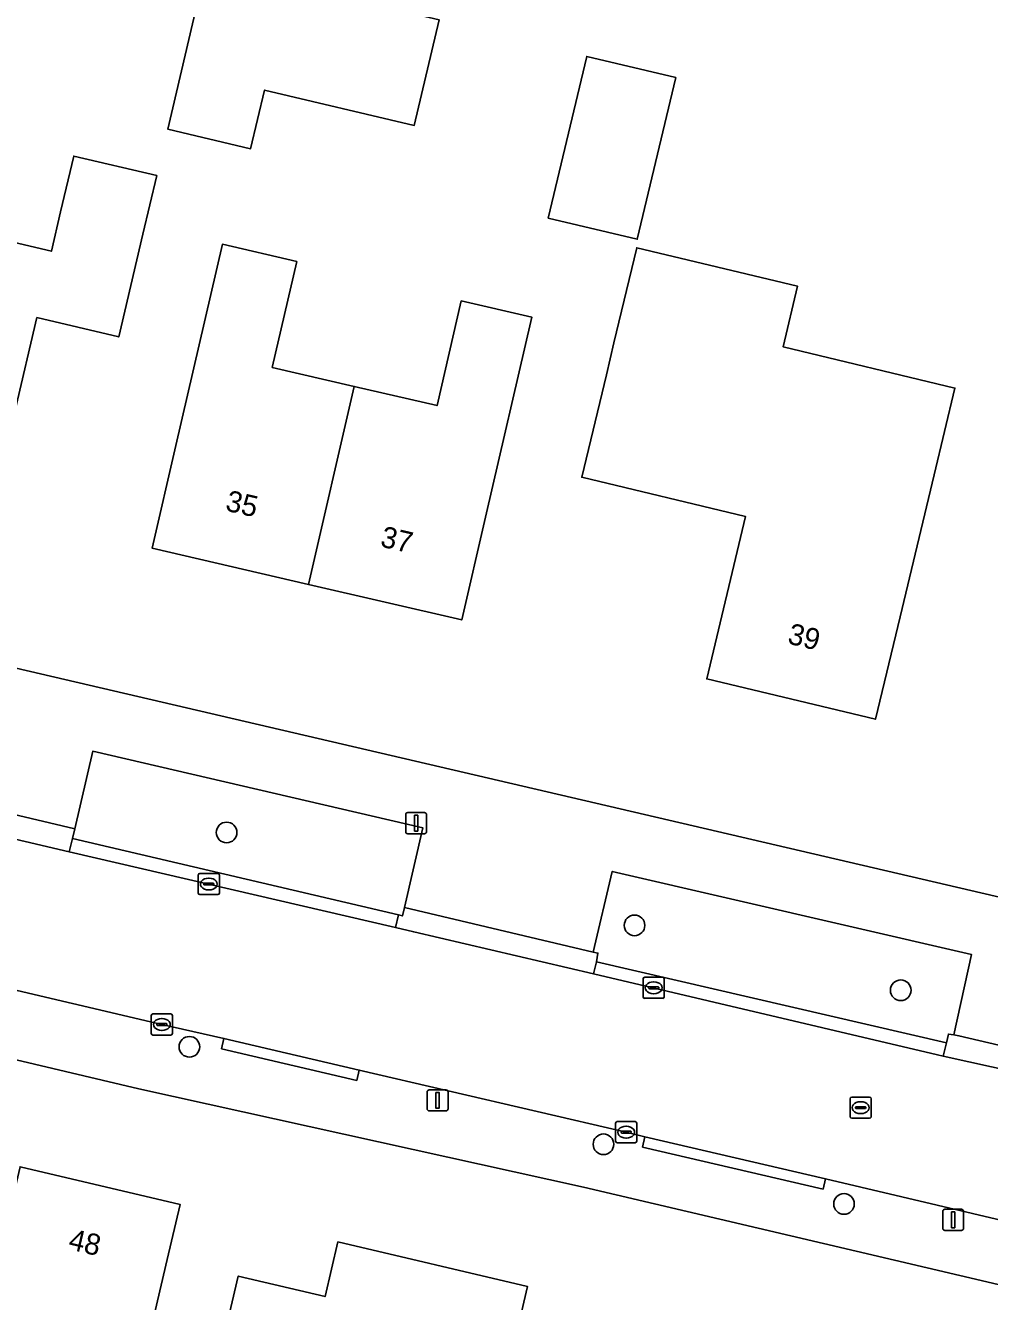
# Model space of a CAD drawing. Extents: x 162184 to 163154, y 385507 to 386516.
# Drawn here: x 162630.3 to 162676, y 385817.6 to 385878.1 of the extents above; entities that cross this region are included whole.
import ezdxf

# ---------------------------------------------------------------- set-up
doc = ezdxf.new("R2010")
doc.units = 0
for name, color, linetype in [('IMGEO_Boom', 7, 'Continuous'), ('IMGEO_Erf', 7, 'Continuous'), ('IMGEO_Groenvoorziening', 7, 'Continuous'), ('IMGEO_Kolk', 7, 'Continuous'), ('IMGEO_Lichtmast', 7, 'Continuous'), ('IMGEO_Pand', 7, 'Continuous'), ('IMGEO_Pand_nummerreeks', 7, 'Continuous'), ('IMGEO_Rijbaan_lokaal_open', 7, 'Continuous'), ('IMGEO_Rioolput', 7, 'Continuous'), ('IMGEO_Voetpad_open', 7, 'Continuous')]:
    doc.layers.add(name, color=color, linetype=linetype)

msp = doc.modelspace()

# ---------------------------------------------------------------- linework, layer by layer
at = {"layer": 'IMGEO_Boom'}
for centre in [(162639.821, 385839.799), (162659.165, 385835.397), (162671.791, 385832.319), (162638.057, 385829.641), (162657.693, 385825.018), (162669.1, 385822.191)]:
    msp.add_circle(centre, 0.489, dxfattribs=at)
at = {"layer": 'IMGEO_Erf'}
for points in [[(162649.904, 385878.319), (162648.723, 385873.317), (162641.619, 385874.994), (162640.961, 385872.21), (162637.027, 385873.14), (162638.858, 385880.909)], [(162519.391, 385873.302), (162708.853, 385829.198)], [(162699.173, 385813.033), (162656.753, 385822.985), (162635.665, 385827.646), (162589.44, 385838.573), (162506.371, 385857.936)], [(162630.025, 385823.952), (162637.617, 385822.17), (162637.005, 385819.56), (162636.146, 385815.902), (162639.516, 385815.111), (162640.375, 385818.769), (162644.49, 385817.803), (162645.097, 385820.389), (162654.087, 385818.279), (162652.945, 385813.412), (162651.884, 385808.893), (162645.19, 385810.464), (162644.958, 385809.475), (162643.186, 385809.891), (162642.433, 385806.685), (162638.063, 385807.711), (162638.332, 385808.855), (162638.219, 385808.881), (162638.703, 385810.943), (162638.545, 385810.98), (162638.06, 385808.918), (162632.544, 385810.213), (162633.135, 385812.73), (162627.689, 385814.008)]]:
    msp.add_lwpolyline(points, dxfattribs=at)
for points in [[(162656.896, 385876.589), (162661.118, 385875.584), (162659.295, 385867.92), (162655.073, 385868.925)], [(162636.506, 385870.937), (162635.85, 385868.163), (162634.707, 385863.295), (162630.822, 385864.207), (162629.793, 385859.826), (162628.67, 385855.046), (162625.13, 385855.878), (162625.383, 385856.954), (162621.583, 385857.847), (162617.805, 385858.735), (162617.558, 385857.684), (162613.986, 385858.523), (162615.13, 385863.391), (162616.916, 385870.993), (162620.447, 385870.164), (162619.874, 385867.725), (162623.666, 385866.834), (162627.538, 385865.924), (162628.065, 385868.165), (162631.511, 385867.355), (162631.948, 385869.215), (162632.571, 385871.867)], [(162650.951, 385864.998), (162654.298, 385864.223), (162652.101, 385854.745), (162650.972, 385849.874), (162643.7, 385851.559), (162636.284, 385853.278), (162637.413, 385858.149), (162639.622, 385867.681), (162643.148, 385866.864), (162641.984, 385861.844), (162645.875, 385860.943), (162649.801, 385860.033)], [(162659.273, 385867.519), (162666.898, 385865.69), (162666.21, 385862.822), (162674.357, 385860.869), (162673.37, 385856.753), (162671.758, 385850.028), (162670.593, 385845.165), (162662.591, 385847.083), (162664.435, 385854.773), (162656.664, 385856.636), (162657.829, 385861.499), (162658.191, 385863.008)]]:
    msp.add_lwpolyline(points, close=True, dxfattribs=at)
at = {"layer": 'IMGEO_Groenvoorziening'}
for points in [[(162649.129, 385840.013), (162633.475, 385843.651), (162632.616, 385839.977), (162632.507, 385839.511), (162647.978, 385835.893), (162648.161, 385835.843), (162648.254, 385836.243)], [(162675.153, 385834.012), (162658.107, 385837.957), (162657.207, 385834.121), (162657.428, 385834.085), (162657.358, 385833.668), (162673.955, 385829.832), (162674.055, 385830.239), (162674.313, 385830.2)]]:
    msp.add_lwpolyline(points, close=True, dxfattribs=at)
at = {"layer": 'IMGEO_Kolk'}
for p, q in [((162638.475, 385836.928), (162638.475, 385837.78)), ((162638.55, 385837.854), (162639.402, 385837.854)), ((162638.734, 385837.348), (162638.734, 385837.36)), ((162638.777, 385837.397), (162639.175, 385837.397)), ((162638.963, 385837.634), (162638.988, 385837.634)), ((162639.218, 385837.36), (162639.218, 385837.348)), ((162639.476, 385837.78), (162639.476, 385836.928)), ((162639.402, 385836.854), (162638.55, 385836.854)), ((162639.172, 385837.311), (162638.774, 385837.311)), ((162638.986, 385837.074), (162638.961, 385837.074)), ((162659.575, 385832.012), (162659.575, 385832.864)), ((162659.65, 385832.938), (162660.502, 385832.938)), ((162660.063, 385832.718), (162660.088, 385832.718)), ((162660.576, 385832.864), (162660.576, 385832.012)), ((162660.502, 385831.938), (162659.65, 385831.938)), ((162659.834, 385832.432), (162659.834, 385832.444)), ((162660.272, 385832.395), (162659.874, 385832.395)), ((162659.877, 385832.481), (162660.275, 385832.481)), ((162660.086, 385832.158), (162660.061, 385832.158)), ((162660.318, 385832.444), (162660.318, 385832.432)), ((162636.249, 385830.272), (162636.249, 385831.124)), ((162636.324, 385831.198), (162637.176, 385831.198)), ((162636.508, 385830.692), (162636.508, 385830.704)), ((162636.551, 385830.741), (162636.949, 385830.741)), ((162636.737, 385830.978), (162636.762, 385830.978)), ((162636.992, 385830.704), (162636.992, 385830.692)), ((162637.25, 385831.124), (162637.25, 385830.272)), ((162637.176, 385830.198), (162636.324, 385830.198)), ((162636.946, 385830.655), (162636.548, 385830.655)), ((162636.76, 385830.418), (162636.735, 385830.418)), ((162658.27, 385825.166), (162658.27, 385826.018)), ((162658.345, 385826.092), (162659.197, 385826.092)), ((162658.758, 385825.872), (162658.783, 385825.872)), ((162659.271, 385826.018), (162659.271, 385825.166)), ((162658.529, 385825.586), (162658.529, 385825.598)), ((162658.967, 385825.549), (162658.569, 385825.549)), ((162658.572, 385825.635), (162658.97, 385825.635)), ((162658.781, 385825.312), (162658.756, 385825.312)), ((162659.013, 385825.598), (162659.013, 385825.586)), ((162659.197, 385825.092), (162658.345, 385825.092))]:
    msp.add_line(p, q, dxfattribs=at)
for points in [[(162638.475, 385836.928), (162638.475, 385837.78)], [(162638.55, 385837.854), (162639.402, 385837.854)], [(162639.476, 385837.78), (162639.476, 385836.928)], [(162639.402, 385836.854), (162638.55, 385836.854)], [(162659.575, 385832.012), (162659.575, 385832.864)], [(162659.65, 385832.938), (162660.502, 385832.938)], [(162660.576, 385832.864), (162660.576, 385832.012)], [(162660.502, 385831.938), (162659.65, 385831.938)], [(162636.249, 385830.272), (162636.249, 385831.124)], [(162636.324, 385831.198), (162637.176, 385831.198)], [(162637.25, 385831.124), (162637.25, 385830.272)], [(162637.176, 385830.198), (162636.324, 385830.198)], [(162658.27, 385825.166), (162658.27, 385826.018)], [(162658.345, 385826.092), (162659.197, 385826.092)], [(162659.271, 385826.018), (162659.271, 385825.166)], [(162659.197, 385825.092), (162658.345, 385825.092)]]:
    msp.add_lwpolyline(points, dxfattribs=at)
for centre, radius, start, end in [((162638.552, 385837.778), 0.0765, 91.55205, 178.44795), ((162638.552, 385837.778), 0.0765, 91.55205, 178.44795), ((162638.774, 385837.357), 0.0403, 85.87752, 175.75265), ((162638.771, 385837.347), 0.0366, 178.93798, 274.71019), ((162639.175, 385837.354), 0.043, 264.86636, 352.45326), ((162639.179, 385837.359), 0.0386, 1.73085, 96.63898), ((162639.4, 385837.778), 0.0765, 1.55205, 88.44795), ((162639.4, 385837.778), 0.0765, 1.55205, 88.44795), ((162638.552, 385836.93), 0.0765, 181.55205, 268.44795), ((162638.552, 385836.93), 0.0765, 181.55205, 268.44795), ((162639.4, 385836.93), 0.0765, 271.55205, 358.44795), ((162639.4, 385836.93), 0.0765, 271.55205, 358.44795), ((162659.652, 385832.862), 0.0765, 91.55205, 178.44795), ((162659.652, 385832.862), 0.0765, 91.55205, 178.44795), ((162660.5, 385832.862), 0.0765, 1.55205, 88.44795), ((162660.5, 385832.862), 0.0765, 1.55205, 88.44795), ((162659.652, 385832.014), 0.0765, 181.55205, 268.44795), ((162659.652, 385832.014), 0.0765, 181.55205, 268.44795), ((162659.874, 385832.441), 0.0403, 85.87752, 175.75265), ((162659.871, 385832.431), 0.0366, 178.93798, 274.71019), ((162660.275, 385832.438), 0.043, 264.86636, 352.45326), ((162660.279, 385832.443), 0.0386, 1.73085, 96.63898), ((162660.5, 385832.014), 0.0765, 271.55205, 358.44795), ((162660.5, 385832.014), 0.0765, 271.55205, 358.44795), ((162636.326, 385831.122), 0.0765, 91.55205, 178.44795), ((162636.326, 385831.122), 0.0765, 91.55205, 178.44795), ((162636.548, 385830.701), 0.0403, 85.87752, 175.75265), ((162636.545, 385830.691), 0.0366, 178.93798, 274.71019), ((162636.949, 385830.698), 0.043, 264.86636, 352.45326), ((162636.953, 385830.703), 0.0386, 1.73085, 96.63898), ((162637.174, 385831.122), 0.0765, 1.55205, 88.44795), ((162637.174, 385831.122), 0.0765, 1.55205, 88.44795), ((162636.326, 385830.274), 0.0765, 181.55205, 268.44795), ((162636.326, 385830.274), 0.0765, 181.55205, 268.44795), ((162637.174, 385830.274), 0.0765, 271.55205, 358.44795), ((162637.174, 385830.274), 0.0765, 271.55205, 358.44795), ((162658.347, 385826.016), 0.0765, 91.55205, 178.44795), ((162658.347, 385826.016), 0.0765, 91.55205, 178.44795), ((162659.195, 385826.016), 0.0765, 1.55205, 88.44795), ((162659.195, 385826.016), 0.0765, 1.55205, 88.44795), ((162658.569, 385825.595), 0.0403, 85.87752, 175.75265), ((162658.566, 385825.585), 0.0366, 178.93798, 274.71019), ((162658.97, 385825.592), 0.043, 264.86636, 352.45326), ((162658.974, 385825.597), 0.0386, 1.73085, 96.63898), ((162658.347, 385825.168), 0.0765, 181.55205, 268.44795), ((162658.347, 385825.168), 0.0765, 181.55205, 268.44795), ((162659.195, 385825.168), 0.0765, 271.55205, 358.44795), ((162659.195, 385825.168), 0.0765, 271.55205, 358.44795)]:
    msp.add_arc(centre, radius, start, end, dxfattribs=at)
for centre, major_axis, ratio, start_param, end_param in [((162638.962, 385837.354), (-0.387, 0.002), 0.722429, 4.712389, 7.853982), ((162638.987, 385837.354), (-0.39, 0.002), 0.717154, 1.570796, 4.712389), ((162660.062, 385832.438), (-0.387, 0.002), 0.722429, 4.712389, 7.853982), ((162660.087, 385832.438), (-0.39, 0.002), 0.717154, 1.570796, 4.712389), ((162636.736, 385830.698), (-0.387, 0.002), 0.722429, 4.712389, 7.853982), ((162636.761, 385830.698), (-0.39, 0.002), 0.717154, 1.570796, 4.712389), ((162658.757, 385825.592), (-0.387, 0.002), 0.722429, 4.712389, 7.853982), ((162658.782, 385825.592), (-0.39, 0.002), 0.717154, 1.570796, 4.712389)]:
    msp.add_ellipse(centre, major_axis=major_axis, ratio=ratio, start_param=start_param, end_param=end_param, dxfattribs=at)
at = {"layer": 'IMGEO_Lichtmast'}
for p, q in [((162648.313, 385839.841), (162648.313, 385840.641)), ((162648.313, 385840.641), (162648.313, 385839.841)), ((162648.413, 385840.741), (162649.203, 385840.741)), ((162649.203, 385840.741), (162648.413, 385840.741)), ((162649.303, 385840.641), (162649.303, 385839.841)), ((162649.303, 385839.841), (162649.303, 385840.641)), ((162649.203, 385839.741), (162648.413, 385839.741)), ((162648.413, 385839.741), (162649.203, 385839.741)), ((162649.33, 385826.7), (162649.33, 385827.5)), ((162649.33, 385827.5), (162649.33, 385826.7)), ((162649.43, 385827.6), (162650.22, 385827.6)), ((162650.22, 385827.6), (162649.43, 385827.6)), ((162650.32, 385827.5), (162650.32, 385826.7)), ((162650.32, 385826.7), (162650.32, 385827.5)), ((162650.22, 385826.6), (162649.43, 385826.6)), ((162649.43, 385826.6), (162650.22, 385826.6)), ((162673.781, 385821.039), (162673.781, 385821.839)), ((162673.781, 385821.839), (162673.781, 385821.039)), ((162673.881, 385821.939), (162674.671, 385821.939)), ((162674.671, 385821.939), (162673.881, 385821.939)), ((162674.771, 385821.839), (162674.771, 385821.039)), ((162674.771, 385821.039), (162674.771, 385821.839)), ((162674.671, 385820.939), (162673.881, 385820.939)), ((162673.881, 385820.939), (162674.671, 385820.939))]:
    msp.add_line(p, q, dxfattribs=at)
for points in [[(162648.733, 385840.616), (162648.883, 385840.616), (162648.883, 385839.866), (162648.733, 385839.866), (162648.733, 385840.616)], [(162649.75, 385827.475), (162649.9, 385827.475), (162649.9, 385826.725), (162649.75, 385826.725), (162649.75, 385827.475)], [(162674.201, 385821.814), (162674.351, 385821.814), (162674.351, 385821.064), (162674.201, 385821.064), (162674.201, 385821.814)]]:
    msp.add_lwpolyline(points, dxfattribs=at)
for centre, start, end in [((162648.413, 385840.641), 90, 180), ((162648.413, 385840.641), 90, 180), ((162649.203, 385840.641), 0, 90), ((162649.203, 385840.641), 360, 90), ((162648.413, 385839.841), 180, 270), ((162648.413, 385839.841), 180, 270), ((162649.203, 385839.841), 270, 0), ((162649.203, 385839.841), 270, 0), ((162649.43, 385827.5), 90, 180), ((162649.43, 385827.5), 90, 180), ((162650.22, 385827.5), 0, 90), ((162650.22, 385827.5), 360, 90), ((162649.43, 385826.7), 180, 270), ((162649.43, 385826.7), 180, 270), ((162650.22, 385826.7), 270, 0), ((162650.22, 385826.7), 270, 0), ((162673.881, 385821.839), 90, 180), ((162673.881, 385821.839), 90, 180), ((162674.671, 385821.839), 0, 90), ((162674.671, 385821.839), 360, 90), ((162673.881, 385821.039), 180, 270), ((162673.881, 385821.039), 180, 270), ((162674.671, 385821.039), 270, 0), ((162674.671, 385821.039), 270, 0)]:
    msp.add_arc(centre, 0.1, start, end, dxfattribs=at)
at = {"layer": 'IMGEO_Pand'}
for points in [[(162637.027, 385873.14), (162640.961, 385872.21), (162641.619, 385874.994), (162648.723, 385873.317), (162649.904, 385878.319), (162638.858, 385880.909)], [(162655.073, 385868.925), (162659.295, 385867.92), (162661.118, 385875.584), (162656.896, 385876.589)], [(162630.822, 385864.207), (162634.707, 385863.295), (162635.85, 385868.163), (162636.506, 385870.937), (162632.571, 385871.867), (162631.948, 385869.215), (162631.511, 385867.355), (162628.065, 385868.165), (162627.538, 385865.924), (162623.666, 385866.834), (162621.583, 385857.847), (162625.383, 385856.954), (162625.13, 385855.878), (162628.67, 385855.046), (162629.793, 385859.826)], [(162645.875, 385860.943), (162641.984, 385861.844), (162643.148, 385866.864), (162639.622, 385867.681), (162637.413, 385858.149), (162636.284, 385853.278), (162643.7, 385851.559)], [(162657.829, 385861.499), (162656.664, 385856.636), (162664.435, 385854.773), (162662.591, 385847.083), (162670.593, 385845.165), (162671.758, 385850.028), (162673.37, 385856.753), (162674.357, 385860.869), (162666.21, 385862.822), (162666.898, 385865.69), (162659.273, 385867.519), (162658.191, 385863.008)], [(162643.7, 385851.559), (162650.972, 385849.874), (162652.101, 385854.745), (162654.298, 385864.223), (162650.951, 385864.998), (162649.801, 385860.033), (162645.875, 385860.943)], [(162637.005, 385819.56), (162637.617, 385822.17), (162630.025, 385823.952), (162627.689, 385814.008), (162633.135, 385812.73), (162632.544, 385810.213), (162638.06, 385808.918), (162638.545, 385810.98), (162639.516, 385815.111), (162636.146, 385815.902)], [(162654.087, 385818.279), (162645.097, 385820.389), (162644.49, 385817.803), (162640.375, 385818.769), (162639.516, 385815.111), (162638.545, 385810.98), (162638.703, 385810.943), (162643.186, 385809.891), (162644.958, 385809.475), (162645.19, 385810.464), (162651.884, 385808.893), (162652.945, 385813.412)]]:
    msp.add_lwpolyline(points, close=True, dxfattribs=at)
at = {"layer": 'IMGEO_Rijbaan_lokaal_open'}
msp.add_lwpolyline([(162624.031, 385833.683), (162636.751, 385830.699), (162639.694, 385830.036), (162646.109, 385828.534), (162658.771, 385825.593), (162659.662, 385825.372), (162668.217, 385823.379), (162678.821, 385820.888), (162699.841, 385815.996), (162703.057, 385815.242), (162703.623, 385815.109), (162705.223, 385821.912), (162701.129, 385822.875), (162677.312, 385828.42), (162673.806, 385829.193), (162673.535, 385829.253), (162657.219, 385833.101), (162648.695, 385835.082), (162647.825, 385835.298), (162632.362, 385838.888), (162625.804, 385840.416)], dxfattribs=at)
at = {"layer": 'IMGEO_Rioolput'}
for p, q in [((162669.389, 385826.329), (162669.389, 385827.181)), ((162669.464, 385827.255), (162670.316, 385827.255)), ((162670.39, 385827.181), (162670.39, 385826.329)), ((162669.648, 385826.749), (162669.648, 385826.761)), ((162670.086, 385826.712), (162669.688, 385826.712)), ((162669.691, 385826.798), (162670.089, 385826.798)), ((162669.9, 385826.475), (162669.875, 385826.475)), ((162669.877, 385827.035), (162669.902, 385827.035)), ((162670.132, 385826.761), (162670.132, 385826.749)), ((162670.316, 385826.255), (162669.464, 385826.255))]:
    msp.add_line(p, q, dxfattribs=at)
for points in [[(162669.389, 385826.329), (162669.389, 385827.181)], [(162669.464, 385827.255), (162670.316, 385827.255)], [(162670.39, 385827.181), (162670.39, 385826.329)], [(162670.316, 385826.255), (162669.464, 385826.255)]]:
    msp.add_lwpolyline(points, dxfattribs=at)
for centre, radius, start, end in [((162669.466, 385827.179), 0.0765, 91.55205, 178.44795), ((162669.466, 385827.179), 0.0765, 91.55205, 178.44795), ((162670.314, 385827.179), 0.0765, 1.55205, 88.44795), ((162670.314, 385827.179), 0.0765, 1.55205, 88.44795), ((162669.688, 385826.758), 0.0403, 85.87752, 175.75265), ((162669.685, 385826.748), 0.0366, 178.93798, 274.71019), ((162670.089, 385826.755), 0.043, 264.86636, 352.45326), ((162670.093, 385826.76), 0.0386, 1.73085, 96.63898), ((162669.466, 385826.331), 0.0765, 181.55205, 268.44795), ((162669.466, 385826.331), 0.0765, 181.55205, 268.44795), ((162670.314, 385826.331), 0.0765, 271.55205, 358.44795), ((162670.314, 385826.331), 0.0765, 271.55205, 358.44795)]:
    msp.add_arc(centre, radius, start, end, dxfattribs=at)
for centre, major_axis, ratio, start_param, end_param in [((162669.876, 385826.755), (-0.387, 0.002), 0.722429, 4.712389, 7.853982), ((162669.901, 385826.755), (-0.39, 0.002), 0.717154, 1.570796, 4.712389)]:
    msp.add_ellipse(centre, major_axis=major_axis, ratio=ratio, start_param=start_param, end_param=end_param, dxfattribs=at)
at = {"layer": 'IMGEO_Voetpad_open'}
for points in [[(162708.853, 385829.198), (162519.391, 385873.302)], [(162496.672, 385860.214), (162498.12, 385859.904), (162506.313, 385857.957), (162506.371, 385857.936), (162589.44, 385838.573), (162635.665, 385827.646), (162656.753, 385822.985), (162699.173, 385813.033)], [(162626.065, 385841.525), (162632.616, 385839.977), (162633.475, 385843.651), (162649.129, 385840.013), (162648.254, 385836.243), (162657.207, 385834.121), (162658.107, 385837.957), (162675.153, 385834.012), (162674.313, 385830.2), (162674.551, 385830.164), (162676.924, 385829.599), (162677.781, 385833.376), (162707.767, 385826.491)], [(162700.467, 385809.183), (162700.641, 385809.435), (162703.623, 385815.109), (162703.057, 385815.242), (162699.841, 385815.996), (162678.821, 385820.888), (162668.217, 385823.379), (162668.104, 385822.893), (162659.549, 385824.886), (162659.662, 385825.372), (162658.771, 385825.593), (162646.109, 385828.534), (162645.996, 385828.048), (162639.581, 385829.55), (162639.694, 385830.036), (162636.751, 385830.699), (162624.031, 385833.683), (162623.919, 385833.196), (162617.481, 385834.688), (162617.593, 385835.175), (162616.709, 385835.361), (162602.566, 385838.654)]]:
    msp.add_lwpolyline(points, dxfattribs=at)
for points in [[(162626.065, 385841.525), (162625.946, 385841.029), (162625.804, 385840.416), (162632.362, 385838.888), (162632.507, 385839.511), (162632.616, 385839.977)], [(162632.507, 385839.511), (162632.362, 385838.888), (162647.825, 385835.298), (162647.978, 385835.893)], [(162648.254, 385836.243), (162648.161, 385835.843), (162647.978, 385835.893), (162647.825, 385835.298), (162648.695, 385835.082), (162657.219, 385833.101), (162657.358, 385833.668), (162657.428, 385834.085), (162657.207, 385834.121)], [(162673.955, 385829.832), (162657.358, 385833.668), (162657.219, 385833.101), (162673.535, 385829.253), (162673.806, 385829.193)], [(162676.924, 385829.599), (162674.551, 385830.164), (162674.313, 385830.2), (162674.055, 385830.239), (162673.955, 385829.832), (162673.806, 385829.193), (162677.312, 385828.42), (162677.457, 385829.037), (162677.533, 385829.36)], [(162639.694, 385830.036), (162639.581, 385829.55), (162645.996, 385828.048), (162646.109, 385828.534)], [(162659.662, 385825.372), (162659.549, 385824.886), (162668.104, 385822.893), (162668.217, 385823.379)]]:
    msp.add_lwpolyline(points, close=True, dxfattribs=at)

# ---------------------------------------------------------------- texts
at = {"layer": 'IMGEO_Pand_nummerreeks'}
for s, rotation, p in [('35', 346.95183, (162639.72, 385855.068)), ('37', 346.95183, (162647.064, 385853.366)), ('39', 346.52106, (162666.376, 385848.767)), ('48', 346.78759, (162632.27, 385820.056))]:
    msp.add_text(s, height=1, rotation=rotation, dxfattribs=at).set_placement(p)

doc.saveas('drawing.dxf')
